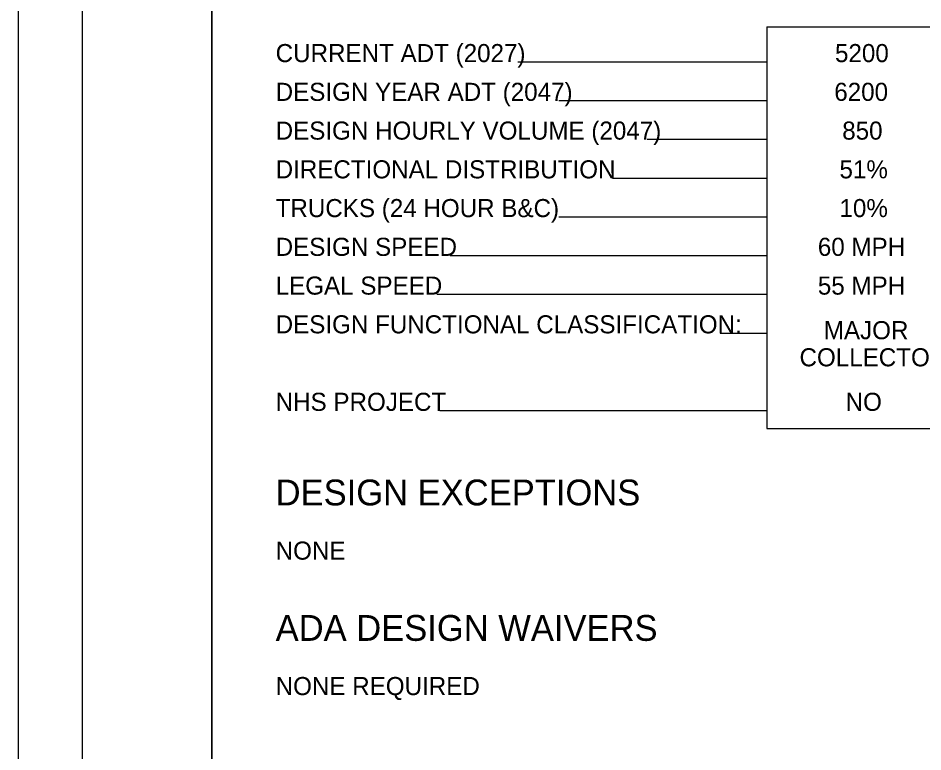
# Model space of a CAD drawing. Extents: x 0 to 34, y 0 to 22.
# Drawn here: x 0 to 7.01, y 6.3 to 11.98 of the extents above; entities that cross this region are included whole.
import ezdxf

# ---------------------------------------------------------------- set-up
doc = ezdxf.new("R2010")
doc.units = 0
for name, color, linetype in [('Default', 7, 'Continuous'), ('SH_Border', 7, 'Continuous'), ('SH_Cut_Line', 7, 'Continuous'), ('SH_Data', 7, 'Continuous'), ('SH_Text', 7, 'Continuous')]:
    doc.layers.add(name, color=color, linetype=linetype)

msp = doc.modelspace()

# ---------------------------------------------------------------- linework, layer by layer
at = {"layer": 'Default'}
for p, q in [((5.799, 11.9098), (7.299, 11.9098)), ((5.799, 11.9098), (5.799, 8.8002)), ((5.799, 8.8002), (7.299, 8.8002))]:
    msp.add_line(p, q, dxfattribs=at)
at = {"layer": 'SH_Border'}
for points in [[(0.5, 21.5), (1.5, 21.5), (1.5, 0.5), (0.5, 0.5)], [(1.5, 21.5), (33.5, 21.5), (33.5, 0.5), (1.5, 0.5)]]:
    msp.add_lwpolyline(points, close=True, dxfattribs=at)
at = {"layer": 'SH_Cut_Line'}
msp.add_lwpolyline([(0, 0), (34, 0), (34, 22), (0, 22)], close=True, dxfattribs=at)
at = {"layer": 'SH_Data'}
for p, q in [((5.799, 11.6362), (3.871, 11.6362)), ((5.799, 11.3362), (4.1885, 11.3362)), ((5.799, 11.0362), (4.8723, 11.0362)), ((5.799, 10.7362), (4.6037, 10.7362)), ((5.799, 10.4362), (4.1885, 10.4362)), ((5.799, 10.1362), (3.346, 10.1362)), ((5.799, 9.8362), (3.2422, 9.8362)), ((5.799, 9.5362), (5.4363, 9.5362)), ((5.799, 8.9362), (3.2669, 8.9362))]:
    msp.add_line(p, q, dxfattribs=at)

# ---------------------------------------------------------------- texts
at = {"layer": 'SH_Text'}
for s, height, p in [('CURRENT ADT (2027)', 0.14, (1.9944, 11.6362)), ('5200', 0.14, (6.3258, 11.6362)), ('DESIGN YEAR ADT (2047)', 0.14, (1.9944, 11.3362)), ('6200', 0.14, (6.3202, 11.3362)), ('DESIGN HOURLY VOLUME (2047)', 0.14, (1.9944, 11.0362)), ('850', 0.14, (6.3817, 11.0362)), ('DIRECTIONAL DISTRIBUTION', 0.14, (1.9944, 10.7362)), ('51%', 0.14, (6.3604, 10.7362)), ('TRUCKS (24 HOUR B&C)', 0.14, (1.9944, 10.4362)), ('10%', 0.14, (6.3604, 10.4362)), ('DESIGN SPEED', 0.14, (1.9944, 10.1362)), ('60 MPH', 0.14, (6.1929, 10.1362)), ('LEGAL SPEED', 0.14, (1.9944, 9.8362)), ('55 MPH', 0.14, (6.1929, 9.8362)), ('DESIGN FUNCTIONAL CLASSIFICATION:', 0.14, (1.9944, 9.5362)), ('MAJOR', 0.14, (6.2391, 9.491)), ('COLLECTOR', 0.14, (6.051, 9.281)), ('NHS PROJECT', 0.14, (1.9944, 8.9362)), ('NO', 0.14, (6.408, 8.9362)), ('DESIGN EXCEPTIONS', 0.2, (1.9944, 8.2043)), ('NONE', 0.14, (1.9944, 7.7843)), ('ADA DESIGN WAIVERS', 0.2, (1.9944, 7.1556)), ('NONE REQUIRED', 0.14, (1.9944, 6.7356))]:
    msp.add_text(s, height=height, dxfattribs=at).set_placement(p)

doc.saveas('drawing.dxf')
